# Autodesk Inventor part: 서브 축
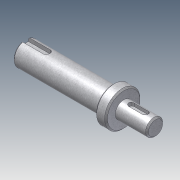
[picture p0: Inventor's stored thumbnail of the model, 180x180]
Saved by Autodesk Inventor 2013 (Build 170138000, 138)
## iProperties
Company: 한국ATC센터
Created: 2014-10
Part Number: 서브 축
Document SubType Name: Modeling
Designer: KYOUNG IL JANG
Density: 7.85 g/cm^3
Mass: 156.705 g
Surface Area: 57.7178 cm^2
Volume: 19.9624 cm^3
Material: 강철
Author: KYOUNG IL JANG
Revision Number: 1
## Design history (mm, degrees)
sketch "스케치1"
  geometry: L1 (-16.331, 0)-(-108.831, 0); L2 (-16.331, 0)-(-16.331, -6); L3 (-16.331, -6)-(-38.831, -6); L4 (-38.831, -12.5)-(-46.5, -12.5); L5 (-46.5, -8.5)-(-108.831, -8.5); L6 (-108.831, -8.5)-(-108.831, 0); L7 (-46.5, -8.5)-(-46.5, -12.5); L8 (-38.831, -6)-(-38.831, -12.5); L9 (-46.5, 12.249)-(-46.5, -12.249) reference; L10 (-38.831, -17)-(-38.831, 17) reference; 2 further points
  constraints: 17 end point, 4 perpendicular, 2 collinear, 2 parallel, 1 horizontal, 1 midpoint, 1 point on line
  dimensions: "d1" = 12 diameter of L3 L1; "d2" = 25 diameter of L4 L1; "d3" = 17 diameter of L5 L1; "d4" = 62.33128 distance of L5.start L5.end (derived); "d18" = 22.5 distance of L2.end L3.end; "d20" = 70 distance between parallel lines of L6 L8
revolve "회전1" sketch "스케치1" stored, may be unused: angle "d5" = 90 deg
chamfer "모따기1" distance "d6" = 1; stored, may be unused: second distance "d7" = 2, angle "d8" = 45 deg
node "작업 평면1"
sketch "스케치2"
  geometry: L1 (11.25, 5)-(11.25, -5) reference; L2 (-5.75, -2)-(4.25, -2); L3 (4.25, 2)-(-5.75, 2); A1 r 2 centre (4.25, 0) between (4.25, -2) and (4.25, 2); A2 r 2 centre (-5.75, 0) between (-5.75, 2) and (-5.75, -2); 2 further points
  constraints: 4 end point, 4 point on circle, 4 tangent, 2 centre point, 1 horizontal alignment, 1 midpoint, 1 parallel, 1 perpendicular
  dimensions: "d9" = 4 distance between parallel lines of L2 L3; "d10" = 14 dimension on A1 A2; "d11" = 5 distance edge to line of A1 L1
extrude "돌출1" cut sketch "스케치2" distance "d12" = 2.5; taper "d13" = 0 deg
node "작업 평면2"
sketch "스케치3"
  geometry: L1 (-31.166, -7.5)-(-31.166, 7.5) reference; L2 (-31.166, 2.5)-(-15.666, 2.5); L3 (-15.666, -2.5)-(-31.166, -2.5); A1 r 2.5 centre (-15.666, 0) between (-15.666, -2.5) and (-15.666, 2.5); 2 further points
  constraints: 4 end point, 2 perpendicular, 2 point on circle, 2 point on line, 2 tangent, 1 centre point, 1 horizontal alignment, 1 midpoint
  dimensions: "d14" = 5 distance between parallel lines of L3 L2; "d15" = 18 dimension on A1 L1
extrude "돌출2" cut sketch "스케치3" distance "d16" = 3; taper "d17" = 0 deg
node "솔리드1"
node "참조4"
node "참조5"
